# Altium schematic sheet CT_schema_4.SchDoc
size 148 x 123 mm
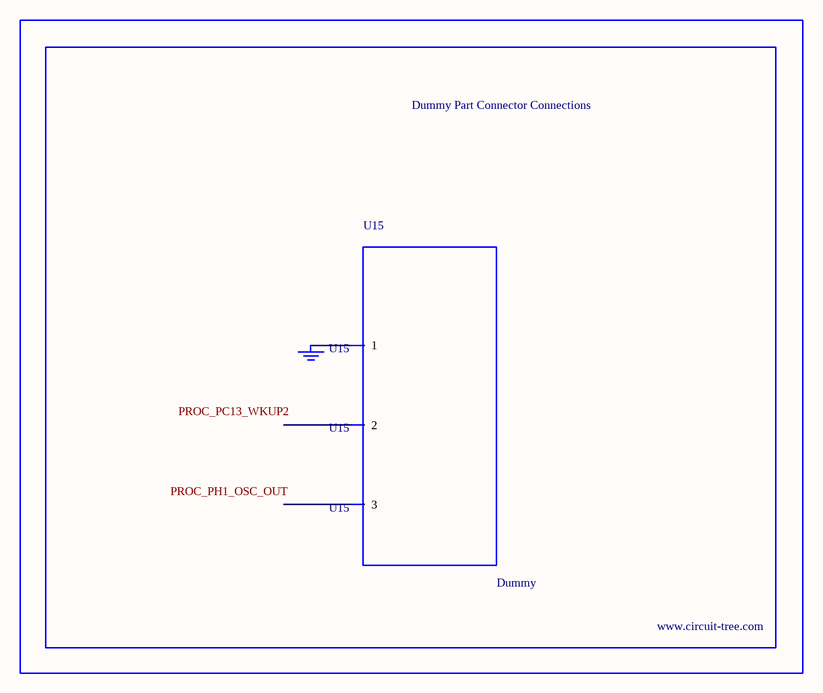
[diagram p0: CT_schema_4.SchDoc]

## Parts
BORDER3  (no value)
GND_INSTANCE_3_0  (no value)
U15  Dummy  [DUMMY_PACKAGE_112]

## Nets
NetGND_INSTANCE_3_0_0: GND_INSTANCE_3_0.0(GND) U15.1

Not connected (* = marked no-connect by the designer): U15 2 3

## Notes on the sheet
- Labels drawn without touching a wire or pin: PROC_PC13_WKUP2, PROC_PH1_OSC_OUT

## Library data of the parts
BORDER3 = BORDER_PAGE3
GND_INSTANCE_3_0 = GND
